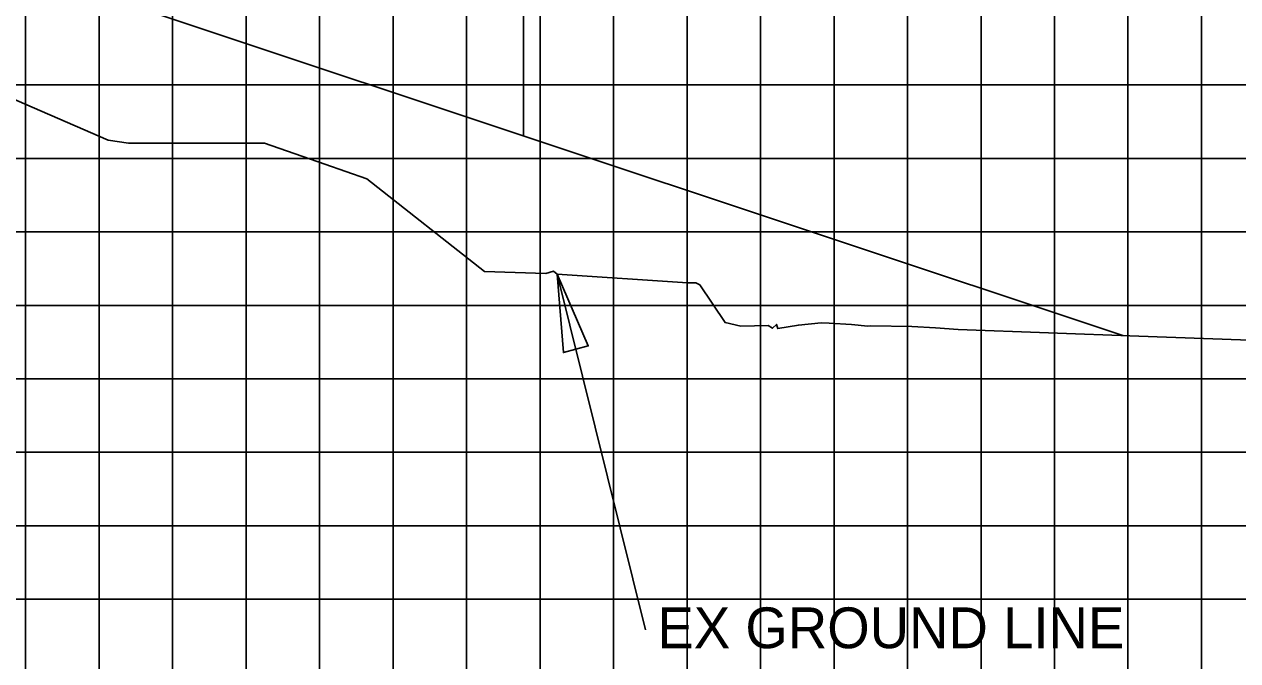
# Model space of a CAD drawing. Extents: x 2193008 to 2198143, y 1236112 to 1237864.
# Drawn here: x 2195468.75 to 2195501.77, y 1237175.43 to 1237192.76 of the extents above; entities that cross this region are included whole.
import ezdxf

# ---------------------------------------------------------------- set-up
doc = ezdxf.new("R2010")
doc.units = 0
for name, color, linetype in [('3', 7, 'Continuous'), ('60', 7, 'Continuous'), ('GSDIMS', 7, 'Continuous'), ('Level 55', 7, 'Continuous'), ('M-ROADS', 7, 'Continuous')]:
    doc.layers.add(name, color=color, linetype=linetype)

msp = doc.modelspace()

# ---------------------------------------------------------------- linework, layer by layer
at = {"layer": '3'}
msp.add_line((2195485.65, 1237176.269), (2195483.25, 1237185.955), dxfattribs=at)
at = {"layer": '60'}
msp.add_lwpolyline([(2195388.783, 1237193.146), (2195389.871, 1237193.142), (2195390.033, 1237193.15), (2195400.033, 1237193.607), (2195412.033, 1237194.155), (2195424.033, 1237194.703), (2195436.033, 1237195.252), (2195448.033, 1237195.8), (2195460.033, 1237195.509), (2195462.033, 1237195.46), (2195465.533, 1237195.32), (2195498.642, 1237184.284)], dxfattribs=at)
at = {"layer": 'GSDIMS'}
msp.add_line((2195482.33, 1237189.721), (2195482.33, 1237202.8), dxfattribs=at)
msp.add_lwpolyline([(2195483.25, 1237185.955), (2195483.418, 1237183.821), (2195484.095, 1237184.004)], close=True, dxfattribs=at)
at = {"layer": 'M-ROADS'}
for p, q in [((2195468.783, 1237163.106), (2195468.783, 1237223.106)), ((2195470.783, 1237163.106), (2195470.783, 1237223.106)), ((2195472.783, 1237163.106), (2195472.783, 1237223.106)), ((2195474.783, 1237163.106), (2195474.783, 1237223.106)), ((2195476.783, 1237163.106), (2195476.783, 1237223.106)), ((2195478.783, 1237163.106), (2195478.783, 1237223.106)), ((2195480.783, 1237163.106), (2195480.783, 1237223.106)), ((2195482.783, 1237163.106), (2195482.783, 1237223.106)), ((2195484.783, 1237163.106), (2195484.783, 1237223.106)), ((2195486.783, 1237163.106), (2195486.783, 1237223.106)), ((2195488.783, 1237163.106), (2195488.783, 1237223.106)), ((2195490.783, 1237163.106), (2195490.783, 1237223.106)), ((2195492.783, 1237163.106), (2195492.783, 1237223.106)), ((2195494.783, 1237163.106), (2195494.783, 1237223.106)), ((2195496.783, 1237163.106), (2195496.783, 1237223.106)), ((2195498.783, 1237163.106), (2195498.783, 1237223.106)), ((2195500.783, 1237163.106), (2195500.783, 1237223.106)), ((2195388.783, 1237191.106), (2195518.783, 1237191.106)), ((2195388.783, 1237189.106), (2195518.783, 1237189.106)), ((2195388.783, 1237187.106), (2195518.783, 1237187.106)), ((2195388.783, 1237185.106), (2195518.783, 1237185.106)), ((2195388.783, 1237183.106), (2195518.783, 1237183.106)), ((2195388.783, 1237181.106), (2195518.783, 1237181.106)), ((2195388.783, 1237179.106), (2195518.783, 1237179.106)), ((2195388.783, 1237177.106), (2195518.783, 1237177.106))]:
    msp.add_line(p, q, dxfattribs=at)
msp.add_lwpolyline([(2195466.949, 1237191.373), (2195471.031, 1237189.607), (2195471.579, 1237189.526), (2195473.786, 1237189.526), (2195475.283, 1237189.526), (2195476.924, 1237188.949), (2195478.068, 1237188.547), (2195481.273, 1237186.029), (2195482.94, 1237185.976), (2195483.149, 1237186.034), (2195483.25, 1237185.955), (2195486.794, 1237185.716), (2195487.022, 1237185.716), (2195487.127, 1237185.667), (2195487.816, 1237184.637), (2195488.249, 1237184.54), (2195488.993, 1237184.56), (2195489.105, 1237184.482), (2195489.214, 1237184.586), (2195489.253, 1237184.475), (2195489.812, 1237184.57), (2195490.429, 1237184.627), (2195490.65, 1237184.619), (2195491.256, 1237184.589), (2195491.701, 1237184.54), (2195491.789, 1237184.552), (2195492.9, 1237184.534), (2195493.547, 1237184.495), (2195494.166, 1237184.452), (2195499.076, 1237184.268), (2195505.615, 1237184.028)], dxfattribs=at)

# ---------------------------------------------------------------- texts
at = {"layer": 'Level 55'}
msp.add_text('EX GROUND LINE', height=1.11046, dxfattribs=at).set_placement((2195485.977, 1237175.773))

doc.saveas('drawing.dxf')
